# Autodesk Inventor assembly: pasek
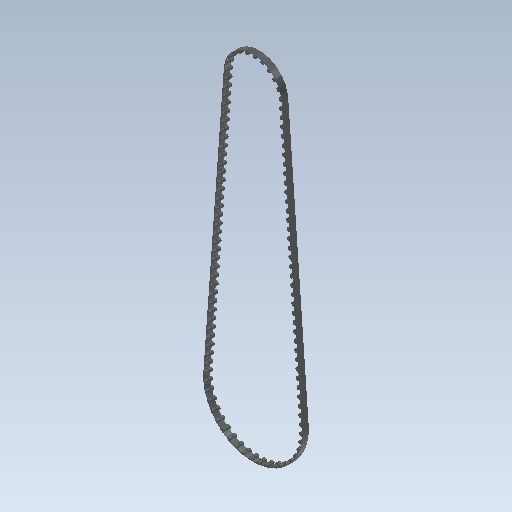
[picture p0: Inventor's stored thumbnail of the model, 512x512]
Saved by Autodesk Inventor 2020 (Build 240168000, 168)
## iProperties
Created: 2015-11
Part Number: pasek
Material: Ogólny
Document SubType Name: Assembly
Designer: Tomasz
Sending System: SolidWorks 2017
Last Author: Tomasz
Last Saved: 2017-11-19
Author: Tomasz
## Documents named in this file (3)
- C:\Users\bruno\Documents\1-Cours-2020-21\1STI2D-2020-21\IT\6. Antivol\Inventor-Antivol\INVENTOR 2018_Steel Hardtail B+\pasek.iam
- C:\Users\bruno\Documents\1-Cours-2020-21\1STI2D-2020-21\IT\6. Antivol\Inventor-Antivol\INVENTOR 2018_Steel Hardtail B+\szkic pasek.ipt
- C:\Users\bruno\Documents\1-Cours-2020-21\1STI2D-2020-21\IT\6. Antivol\Inventor-Antivol\INVENTOR 2018_Steel Hardtail B+\z_X2_0105_X0_bek.ipt
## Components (103 placed, 2 different names)
1. szkic pasek:1
2. z_X2_0105_X0_bek:1
3. z_X2_0105_X0_bek:2
4. z_X2_0105_X0_bek:3
5. z_X2_0105_X0_bek:4
6. z_X2_0105_X0_bek:5
7. z_X2_0105_X0_bek:6
8. z_X2_0105_X0_bek:7
9. z_X2_0105_X0_bek:8
10. z_X2_0105_X0_bek:9
11. z_X2_0105_X0_bek:10
12. z_X2_0105_X0_bek:11
13. z_X2_0105_X0_bek:12
14. z_X2_0105_X0_bek:13
15. z_X2_0105_X0_bek:14
16. z_X2_0105_X0_bek:15
17. z_X2_0105_X0_bek:16
18. z_X2_0105_X0_bek:17
19. z_X2_0105_X0_bek:18
20. z_X2_0105_X0_bek:19
21. z_X2_0105_X0_bek:20
22. z_X2_0105_X0_bek:21
23. z_X2_0105_X0_bek:22
24. z_X2_0105_X0_bek:23
25. z_X2_0105_X0_bek:24
26. z_X2_0105_X0_bek:25
27. z_X2_0105_X0_bek:26
28. z_X2_0105_X0_bek:27
29. z_X2_0105_X0_bek:28
30. z_X2_0105_X0_bek:29
31. z_X2_0105_X0_bek:30
32. z_X2_0105_X0_bek:31
33. z_X2_0105_X0_bek:32
34. z_X2_0105_X0_bek:33
35. z_X2_0105_X0_bek:34
36. z_X2_0105_X0_bek:35
37. z_X2_0105_X0_bek:36
38. z_X2_0105_X0_bek:37
39. z_X2_0105_X0_bek:38
40. z_X2_0105_X0_bek:39
41. z_X2_0105_X0_bek:40
42. z_X2_0105_X0_bek:41
43. z_X2_0105_X0_bek:42
44. z_X2_0105_X0_bek:43
45. z_X2_0105_X0_bek:44
46. z_X2_0105_X0_bek:45
47. z_X2_0105_X0_bek:46
48. z_X2_0105_X0_bek:47
49. z_X2_0105_X0_bek:48
50. z_X2_0105_X0_bek:49
51. z_X2_0105_X0_bek:50
52. z_X2_0105_X0_bek:51
53. z_X2_0105_X0_bek:52
54. z_X2_0105_X0_bek:53
55. z_X2_0105_X0_bek:54
56. z_X2_0105_X0_bek:55
57. z_X2_0105_X0_bek:56
58. z_X2_0105_X0_bek:57
59. z_X2_0105_X0_bek:58
60. z_X2_0105_X0_bek:59
61. z_X2_0105_X0_bek:60
62. z_X2_0105_X0_bek:61
63. z_X2_0105_X0_bek:62
64. z_X2_0105_X0_bek:63
65. z_X2_0105_X0_bek:64
66. z_X2_0105_X0_bek:65
67. z_X2_0105_X0_bek:66
68. z_X2_0105_X0_bek:67
69. z_X2_0105_X0_bek:68
70. z_X2_0105_X0_bek:69
71. z_X2_0105_X0_bek:70
72. z_X2_0105_X0_bek:71
73. z_X2_0105_X0_bek:72
74. z_X2_0105_X0_bek:73
75. z_X2_0105_X0_bek:74
76. z_X2_0105_X0_bek:75
77. z_X2_0105_X0_bek:76
78. z_X2_0105_X0_bek:77
79. z_X2_0105_X0_bek:78
80. z_X2_0105_X0_bek:79
81. z_X2_0105_X0_bek:80
82. z_X2_0105_X0_bek:81
83. z_X2_0105_X0_bek:82
84. z_X2_0105_X0_bek:83
85. z_X2_0105_X0_bek:84
86. z_X2_0105_X0_bek:85
87. z_X2_0105_X0_bek:86
88. z_X2_0105_X0_bek:87
89. z_X2_0105_X0_bek:88
90. z_X2_0105_X0_bek:89
91. z_X2_0105_X0_bek:90
92. z_X2_0105_X0_bek:91
93. z_X2_0105_X0_bek:92
94. z_X2_0105_X0_bek:93
95. z_X2_0105_X0_bek:94
96. z_X2_0105_X0_bek:95
97. z_X2_0105_X0_bek:96
98. z_X2_0105_X0_bek:97
99. z_X2_0105_X0_bek:98
100. z_X2_0105_X0_bek:99
101. z_X2_0105_X0_bek:100
102. z_X2_0105_X0_bek:101
103. z_X2_0105_X0_bek:102
